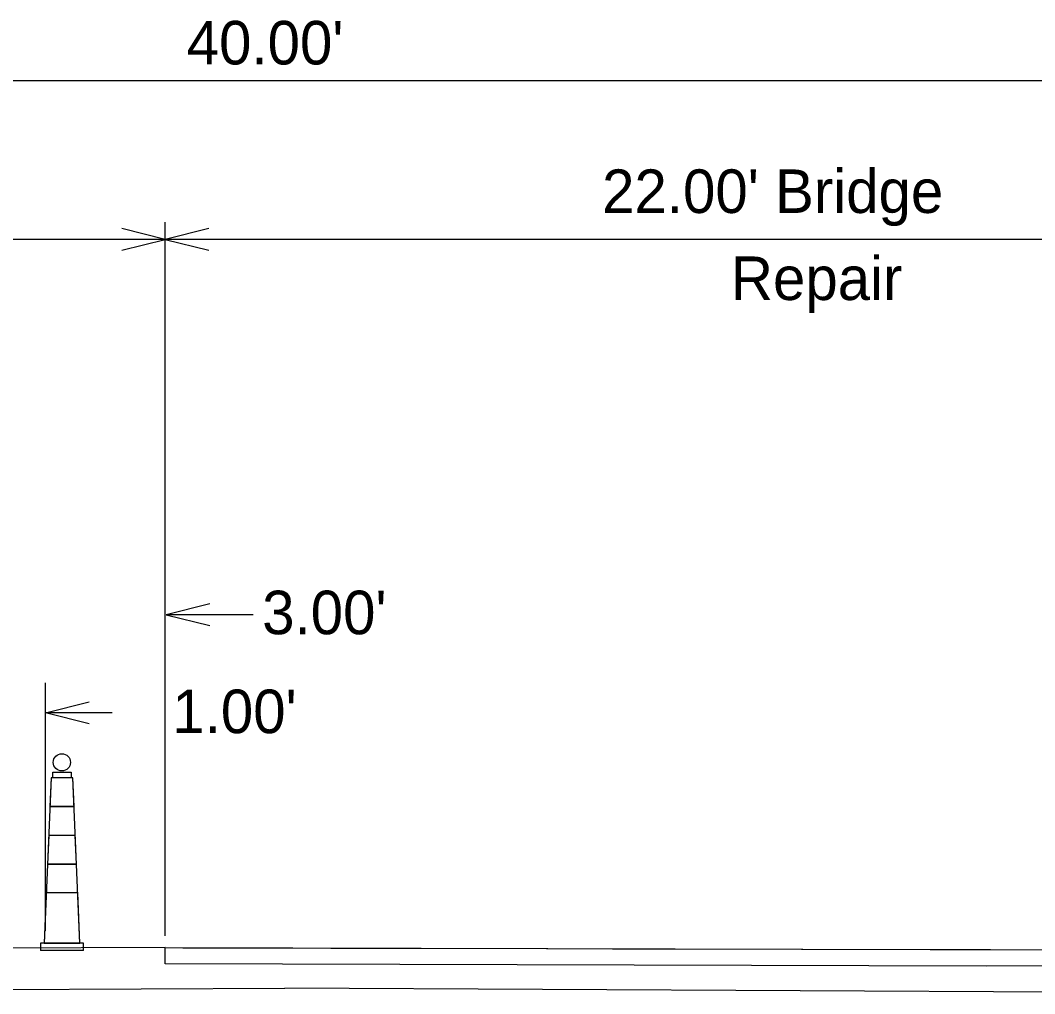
# Model space of a CAD drawing. Extents: x 8410 to 81668, y 7924 to 12712.
# Drawn here: x 11562 to 12091, y 8474 to 8982 of the extents above; entities that cross this region are included whole.
import ezdxf

# ---------------------------------------------------------------- set-up
doc = ezdxf.new("R2010")
doc.units = 0
for name, color, linetype in [('dsnCellElements', 7, 'Continuous'), ('Level 2', 7, 'Continuous'), ('Level 3', 7, 'Continuous')]:
    doc.layers.add(name, color=color, linetype=linetype)

msp = doc.modelspace()

# ---------------------------------------------------------------- linework, layer by layer
at = {"layer": 'dsnCellElements'}
for p, q in [((11578.08, 8586.99), (11574.33, 8500.74)), ((11578.08, 8586.99), (11577.43, 8571.99)), ((11589.33, 8586.99), (11578.08, 8586.99)), ((11589.33, 8586.99), (11578.08, 8586.99)), ((11593.08, 8500.74), (11589.33, 8586.99)), ((11589.99, 8571.99), (11589.33, 8586.99)), ((11589.99, 8571.99), (11577.43, 8571.99)), ((11577.43, 8571.99), (11589.99, 8571.99)), ((11576.78, 8556.99), (11576.13, 8541.99)), ((11590.64, 8556.99), (11576.78, 8556.99)), ((11590.64, 8556.99), (11576.78, 8556.99)), ((11591.29, 8541.99), (11590.64, 8556.99)), ((11591.29, 8541.99), (11576.13, 8541.99)), ((11576.13, 8541.99), (11591.29, 8541.99)), ((11575.47, 8526.99), (11574.33, 8500.74)), ((11591.94, 8526.99), (11575.47, 8526.99)), ((11591.94, 8526.99), (11575.47, 8526.99)), ((11593.08, 8500.74), (11591.94, 8526.99)), ((11594.96, 8500.74), (11572.46, 8500.74)), ((11572.46, 8500.74), (11572.46, 8496.99)), ((11574.33, 8500.74), (11593.08, 8500.74)), ((11594.96, 8496.99), (11594.96, 8500.74)), ((11594.96, 8496.99), (11572.46, 8496.99))]:
    msp.add_line(p, q, dxfattribs=at)
msp.add_lwpolyline([(11578.83, 8589.99), (11588.43, 8589.99), (11588.43, 8586.99), (11578.83, 8586.99)], close=True, dxfattribs=at)
msp.add_circle((11583.63, 8595.09), 4.5, dxfattribs=at)
at = {"layer": 'Level 2'}
for p, q in [((12324.31, 8950.66), (11075.73, 8950.66)), ((11637.59, 8504.58), (11637.59, 8876.93)), ((11637.59, 8867.95), (11075.73, 8867.95)), ((12324.31, 8867.95), (11637.59, 8867.95)), ((11683.47, 8672.12), (11638.05, 8672.12)), ((11575.16, 8507.13), (11575.16, 8636.55)), ((11609.86, 8620.91), (11575.16, 8620.91)), ((11134.51, 8474.39), (11700.02, 8477.31)), ((12265.54, 8474.39), (11700.02, 8477.31))]:
    msp.add_line(p, q, dxfattribs=at)
for points in [[(11614.88, 8862.27), (11637.59, 8867.95), (11614.88, 8873.63)], [(11660.3, 8873.63), (11637.59, 8867.95), (11660.3, 8862.27)], [(11660.76, 8677.8), (11638.05, 8672.12), (11660.76, 8666.45)], [(11597.87, 8615.23), (11575.16, 8620.91), (11597.87, 8626.59)]]:
    msp.add_lwpolyline(points, dxfattribs=at)
at = {"layer": 'Level 3'}
for p, q in [((11637.59, 8498.41), (11038.81, 8496.69)), ((11637.59, 8498.41), (12361.24, 8496.69)), ((11637.59, 8489.99), (11637.59, 8494.6)), ((12065.91, 8488.69), (11637.59, 8489.99))]:
    msp.add_line(p, q, dxfattribs=at)
for points in [[(11637.59, 8494.6), (11637.59, 8498.41), (11646.73, 8498.39), (11665.26, 8498.35), (11691.22, 8498.29), (11723.93, 8498.21), (11771.07, 8498.1), (11836.42, 8497.94), (11870.87, 8497.86), (12068.02, 8497.39)], [(12068.02, 8497.39), (12324.31, 8496.78), (12324.31, 8489.23), (12065.91, 8488.69)]]:
    msp.add_lwpolyline(points, dxfattribs=at)

# ---------------------------------------------------------------- texts
at = {"layer": 'Level 2'}
for s, height, p in [("40.00'", 22.709, (11648.75, 8959.2)), ("22.00' Bridge", 22.7091, (11865.47, 8881.72)), ('Repair', 22.709, (11932.7, 8836.3)), ("3.00'", 22.709, (11688.13, 8661.94)), ("1.00'", 22.709, (11641.24, 8610.34))]:
    msp.add_text(s, height=height, dxfattribs=at).set_placement(p)

doc.saveas('drawing.dxf')
